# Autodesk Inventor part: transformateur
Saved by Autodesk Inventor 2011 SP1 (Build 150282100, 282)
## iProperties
Created: 2010-12
Part Number: transformateur
Document SubType Name: Modeling
Designer: eric
Density: 1 g/cm^3
Author: eric
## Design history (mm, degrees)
feature "Base1"
node "Solide1"
node "Corps solides"
node "Corps surfaciques"
